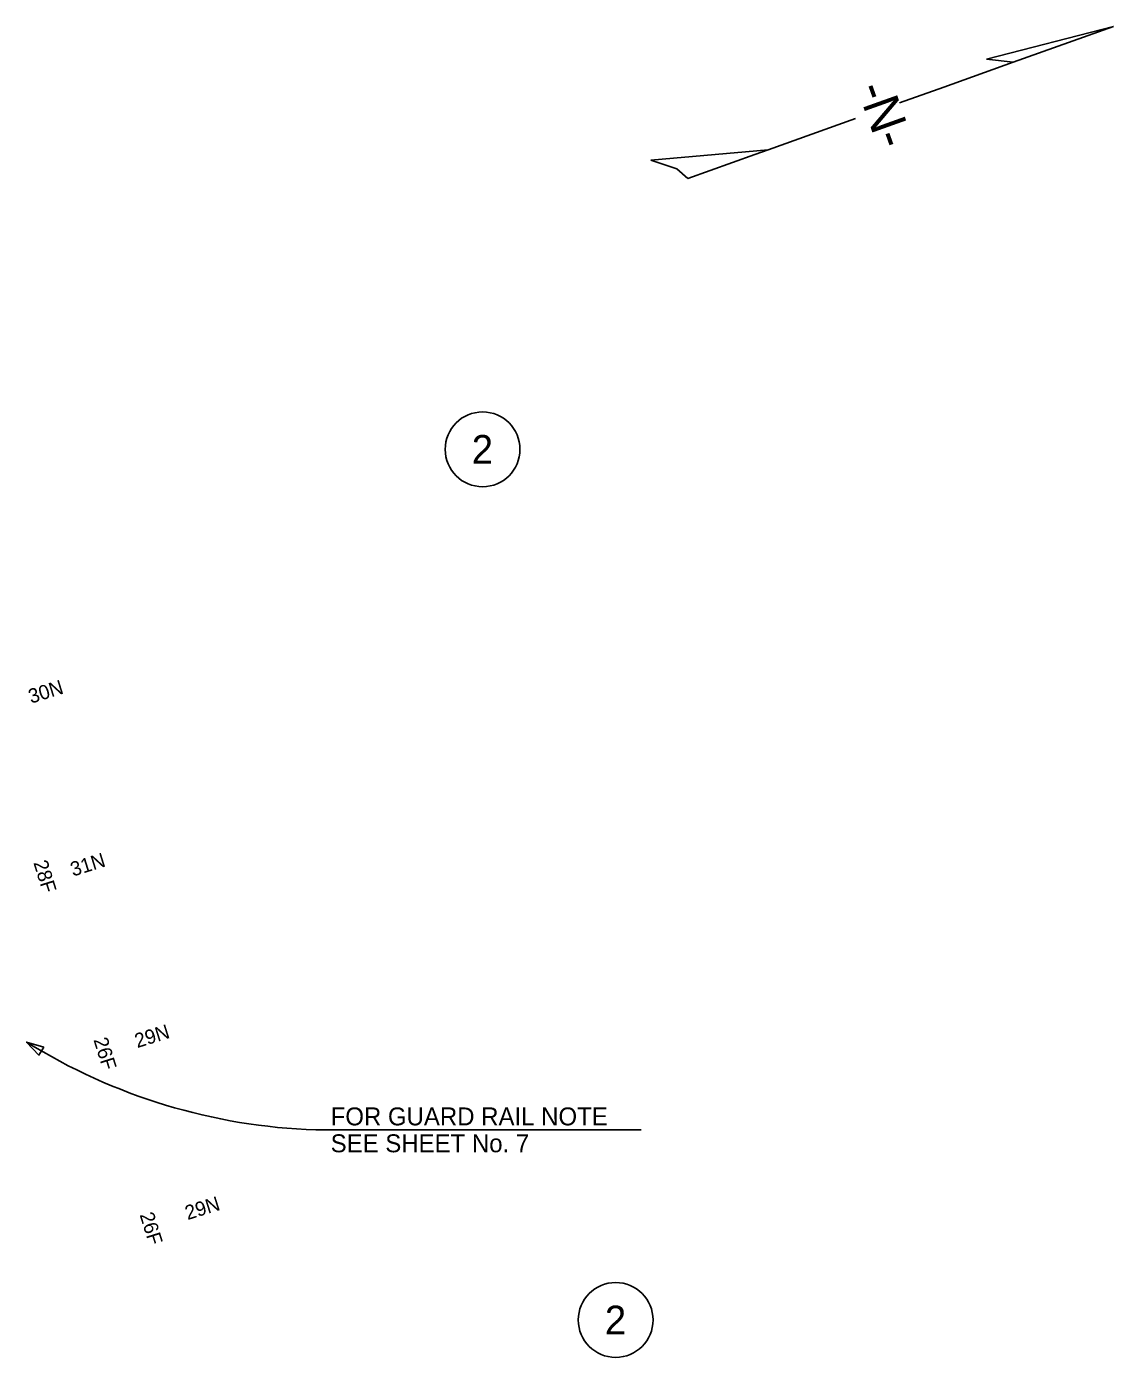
# Model space of a CAD drawing. Extents: x 1964850 to 1967424, y 1116563 to 1122204.
# Drawn here: x 1965975 to 1966278.1, y 1121813 to 1122184 of the extents above; entities that cross this region are included whole.
import ezdxf

# ---------------------------------------------------------------- set-up
doc = ezdxf.new("R2010")
doc.units = 0
for name, color, linetype in [('RD_EX_DV_TX_Prop', 7, 'Continuous'), ('RD_EX_Misc', 7, 'Continuous'), ('RD_PD_TX_CstnLmt', 7, 'Continuous'), ('RD_TX_Drainage', 7, 'Continuous'), ('RD_TX_Misc1', 7, 'Continuous')]:
    doc.layers.add(name, color=color, linetype=linetype)

msp = doc.modelspace()

# ---------------------------------------------------------------- linework, layer by layer
at = {"layer": 'RD_EX_DV_TX_Prop'}
for centre in [(1966102.14, 1122066.15), (1966139.26, 1121823.4)]:
    msp.add_circle(centre, 10.43, dxfattribs=at)
at = {"layer": 'RD_EX_Misc'}
for p, q in [((1966242.66, 1122174.93), (1966278.06, 1122184.02)), ((1966278.06, 1122184.02), (1966250.14, 1122174.06)), ((1966250.14, 1122174.06), (1966230.79, 1122167.16)), ((1966250.14, 1122174.06), (1966242.66, 1122174.93)), ((1966230.79, 1122167.16), (1966218.45, 1122162.76)), ((1966206.14, 1122158.36), (1966181.74, 1122149.66)), ((1966149.08, 1122146.77), (1966181.74, 1122149.66)), ((1966178.05, 1122148.34), (1966159.35, 1122141.68)), ((1966181.74, 1122149.66), (1966178.05, 1122148.34))]:
    msp.add_line(p, q, dxfattribs=at)
msp.add_lwpolyline([(1966159.35, 1122141.68), (1966156.34, 1122144.36), (1966149.08, 1122146.77)], dxfattribs=at)
at = {"layer": 'RD_TX_Misc1'}
msp.add_line((1966146.39, 1121876.41), (1966055.61, 1121876.41), dxfattribs=at)
msp.add_lwpolyline([(1965979.77, 1121899.44), (1965974.98, 1121900.9), (1965978.4, 1121897.24)], close=True, dxfattribs=at)
msp.add_arc((1966060.85, 1122038.66), 162.33, 238.0648, 268.1489, dxfattribs=at)

# ---------------------------------------------------------------- texts
at = {"layer": 'RD_EX_DV_TX_Prop'}
for p in [(1966099.12, 1122062.15), (1966136.24, 1121819.4)]:
    msp.add_text('2', height=8, dxfattribs=at).set_placement(p)
at = {"layer": 'RD_EX_Misc'}
msp.add_text('-N-', height=10, rotation=289.6302, dxfattribs=at).set_placement((1966206.48, 1122166.75))
at = {"layer": 'RD_PD_TX_CstnLmt'}
for s, p in [('28F', (1965976.84, 1121950.91)), ('26F', (1965993.6, 1121901.51)), ('26F', (1966006.47, 1121852.75))]:
    msp.add_text(s, height=4, rotation=287.3569, dxfattribs=at).set_placement(p)
at = {"layer": 'RD_TX_Drainage'}
for s, p in [('30N', (1965976.21, 1121995.22)), ('31N', (1965987.92, 1121947.01)), ('29N', (1966005.84, 1121899.19)), ('29N', (1966019.88, 1121851.23))]:
    msp.add_text(s, height=4, rotation=17.3569, dxfattribs=at).set_placement(p)
at = {"layer": 'RD_TX_Misc1'}
for s, p in [('FOR GUARD RAIL NOTE', (1966059.78, 1121877.66)), ('SEE SHEET No. 7', (1966059.78, 1121870.16))]:
    msp.add_text(s, height=5, dxfattribs=at).set_placement(p)

doc.saveas('drawing.dxf')
